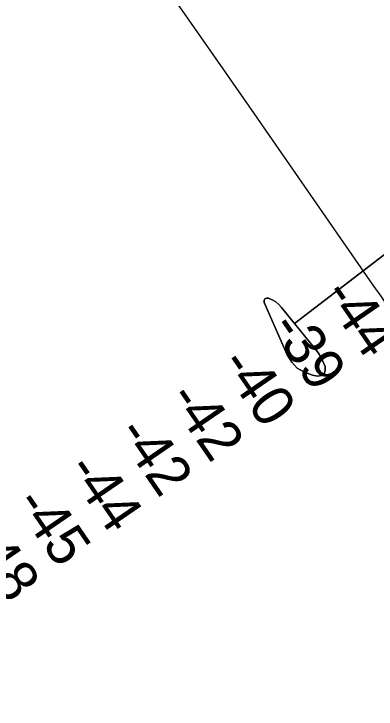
# Model space of a CAD drawing. Extents: x 3892998 to 3931244, y 278583 to 304547.
# Drawn here: x 3912238 to 3912822, y 290539 to 291661 of the extents above; entities that cross this region are included whole.
import ezdxf

# ---------------------------------------------------------------- set-up
doc = ezdxf.new("R2010")
doc.units = 0
for name, color, linetype in [('V-GRID-MAJR', 7, 'Continuous'), ('V-RIVR-EDGE', 7, 'Continuous'), ('V-RIVR-RANG', 7, 'Continuous'), ('V-TOPO-DPTH', 7, 'Continuous'), ('V-TOPO-MAJR', 7, 'Continuous'), ('V-TOPO-MINR', 7, 'Continuous')]:
    doc.layers.add(name, color=color, linetype=linetype)

msp = doc.modelspace()

# ---------------------------------------------------------------- linework, layer by layer
at = {"layer": 'V-GRID-MAJR'}
msp.add_spline([(3897162.9, 290075.2), (3902475.5, 290165.2), (3907788.2, 290256), (3913100.9, 290347.6), (3918413.5, 290440), (3923726.1, 290533.1), (3929038.7, 290627)], degree=3, dxfattribs=at)
at = {"layer": 'V-RIVR-EDGE'}
msp.add_spline([(3909865.8, 290928.2), (3909862.6, 290923.1), (3909860.7, 290922.6), (3909860.7, 290920.7), (3909870.3, 290905.1), (3909881.9, 290877.9), (3909893.5, 290856.5), (3909906.1, 290843.8), (3909921.6, 290817.6), (3909937.1, 290794.7), (3909948.2, 290777.2), (3909977.7, 290734.4), (3910003.4, 290694.5), (3910040.6, 290645.9), (3910078.4, 290595.3), (3910114.2, 290544.2), (3910151.5, 290493.6), (3910182, 290444.5), (3910200.8, 290413.3), (3910226.9, 290368.6), (3910256.9, 290323.8), (3910278.7, 290289.3), (3910307.7, 290250.4), (3910325.2, 290226.5), (3910363.9, 290167.2), (3910391.4, 290124.9), (3910427.7, 290068.9), (3910449.5, 290036.8), (3910504.2, 289956.6), (3910522.1, 289926.9), (3910550.1, 289879.7), (3910562.2, 289857.4), (3910573.3, 289842.3), (3910610.6, 289806.7), (3910620.8, 289794.1), (3910623.2, 289780), (3910634.8, 289764.4), (3910664.8, 289724), (3910692.4, 289689.5), (3910710.8, 289668.1), (3910721, 289660.3), (3910770.9, 289605.3), (3910782.5, 289588.7), (3910807.7, 289548.4), (3910835.7, 289503.6), (3910862.8, 289470), (3910892.3, 289425.8), (3910920.4, 289383.5), (3910948, 289342.6), (3910968.8, 289304.7), (3911000.2, 289260.9), (3911019.6, 289231.7), (3911055.9, 289191.3), (3911085.5, 289159.7), (3911118.9, 289116.8), (3911139.2, 289091.1), (3911161, 289062.3), (3911184.2, 289025.9), (3911223.4, 288981.6), (3911281.5, 288916.4), (3911313, 288876.9), (3911328.5, 288859.4), (3911346.4, 288837.5), (3911371.6, 288801), (3911404.5, 288751.9), (3911426.7, 288715.4), (3911446.6, 288687.7), (3911479, 288646.8), (3911529.4, 288582.1), (3911550.6, 288552.9), (3911609.2, 288468.3), (3911644.5, 288421.1), (3911677, 288378.8), (3911701.2, 288348.1), (3911741.4, 288303.8), (3911770.9, 288264.9), (3911788.8, 288235.7), (3911834.3, 288164.7), (3911857.5, 288130.2), (3911884.6, 288092.7), (3911915.6, 288045.5), (3911921.9, 288035.8), (3911928.6, 288029.9), (3911972.6, 287945.8), (3911992.9, 287906.4), (3912000.6, 287887), (3912014.7, 287866.5), (3912026.8, 287848.1), (3912066.4, 287785.3), (3912084.8, 287750.8), (3912094.5, 287732.8), (3912094.9, 287726), (3912096.8, 287711.4), (3912096.3, 287704.6), (3912095.4, 287700.3), (3912088.6, 287695.9), (3912085.6, 287696.9), (3912073, 287702.3), (3912062.4, 287706.2), (3912054.1, 287706.2), (3912051.2, 287704.3), (3912049.2, 287697.9), (3912054, 287685.8), (3912068.6, 287663.9), (3912113.1, 287586.6), (3912136.7, 287540.9), (3912153.7, 287513.6), (3912163.8, 287503.9), (3912187.6, 287479.6), (3912207.4, 287453.3), (3912216.1, 287446), (3912226.8, 287436.2), (3912240.8, 287416.8), (3912253.4, 287397.8), (3912271.3, 287366.2), (3912283.9, 287341.4), (3912284.8, 287339), (3912290.2, 287338), (3912303.8, 287344.3), (3912317.4, 287350.5), (3912319.8, 287350.5), (3912322.7, 287350.5), (3912327.6, 287345.7), (3912328.5, 287338.4), (3912335.8, 287321.4), (3912348.4, 287300), (3912369.2, 287275.1), (3912380.3, 287265.4), (3912402.1, 287253.2), (3912416.7, 287243.5), (3912434.2, 287238.1), (3912456.9, 287220), (3912481.6, 287183.6), (3912501.9, 287148.1), (3912512.6, 287124.7), (3912531.4, 287085.8), (3912550.3, 287059.6), (3912569.6, 287034.3), (3912593.3, 286996.8), (3912613.7, 286968.1), (3912632, 286936.5), (3912645.1, 286912.7), (3912660.6, 286888.8), (3912675.1, 286867.4), (3912698.3, 286835.3), (3912720.1, 286784.8), (3912737, 286747.8), (3912742.3, 286740), (3912755.3, 286715.2), (3912761.6, 286696.8), (3912774.1, 286660.3), (3912779.9, 286635.5), (3912793.4, 286585.5), (3912797.2, 286569.4), (3912804, 286543.7), (3912804.4, 286532)], degree=3, dxfattribs=at)
at = {"layer": 'V-TOPO-DPTH'}
for points in [[(3913033.3, 291425), (3912690.2, 291161.4), (3912669.3, 291187.3), (3912664.7, 291192.1), (3912659.8, 291196.3), (3912654.2, 291199.7), (3912648.2, 291202.6), (3912644.7, 291202.4), (3912642.2, 291201.3), (3912641.2, 291198.7), (3912641.1, 291195.2), (3912678.2, 291110.8), (3912685.6, 291099.1), (3912694.6, 291089.4), (3912706, 291082.7), (3912719, 291078.1), (3912727, 291076.5), (3912733.4, 291077.7), (3912737.8, 291080.5)], [(3912737.8, 291080.5), (3912739.5, 291085.4), (3912739.3, 291091.9), (3912734.4, 291102.8), (3912732.4, 291107.1), (3912730.1, 291111.1), (3912727.5, 291115), (3912724.7, 291118.8), (3912693, 291157.9), (3912690.2, 291161.4), (3913033.3, 291425), (3913036.6, 291419.3)], [(3912737.8, 291080.5), (3912733.4, 291077.7), (3912727, 291076.5), (3912719, 291078.1), (3912706, 291082.7), (3912694.6, 291089.4), (3912685.6, 291099.1), (3912678.2, 291110.8), (3912641.1, 291195.2), (3912641.2, 291198.7), (3912642.2, 291201.3), (3912644.7, 291202.4), (3912648.2, 291202.6), (3912654.2, 291199.7), (3912659.8, 291196.3), (3912664.7, 291192.1), (3912669.3, 291187.3), (3912724.7, 291118.8), (3912727.5, 291115), (3912730.1, 291111.1), (3912732.4, 291107.1), (3912734.4, 291102.8), (3912739.3, 291091.9), (3912739.5, 291085.4), (3912737.8, 291080.5)]]:
    msp.add_lwpolyline(points, dxfattribs=at)
at = {"layer": 'V-TOPO-MAJR'}
msp.add_lwpolyline([(3912484.1, 291702), (3912531, 291634.5), (3912578, 291567), (3912624.9, 291499.6), (3912816.6, 291223.4), (3912829.1, 291205.4), (3912841.6, 291187.2), (3912853.9, 291169), (3912866.1, 291150.8), (3913227, 290610.6), (3913234.3, 290599.6), (3913241.7, 290588.5), (3913249, 290577.5), (3913256.4, 290566.4), (3913263.8, 290555.4), (3913271.3, 290544.5), (3913279, 290533.7), (3913286.9, 290522.9), (3913293.4, 290514.1), (3913304.6, 290499), (3913315.6, 290483.8), (3913326.4, 290468.5), (3913337.2, 290453.1), (3913674.7, 289963.4)], dxfattribs=at)
at = {"layer": 'V-TOPO-MINR'}
msp.add_lwpolyline([(3912737.8, 291080.5), (3912733.4, 291077.7), (3912727, 291076.5), (3912719, 291078.1), (3912706, 291082.7), (3912694.6, 291089.4), (3912685.6, 291099.1), (3912678.2, 291110.8), (3912641.1, 291195.2), (3912641.2, 291198.7), (3912642.2, 291201.3), (3912644.7, 291202.4), (3912648.2, 291202.6), (3912654.2, 291199.7), (3912659.8, 291196.3), (3912664.7, 291192.1), (3912669.3, 291187.3), (3912724.7, 291118.8), (3912727.5, 291115), (3912730.1, 291111.1), (3912732.4, 291107.1), (3912734.4, 291102.8), (3912739.3, 291091.9), (3912739.5, 291085.4), (3912737.8, 291080.5)], dxfattribs=at)
msp.add_lwpolyline([(3912737.8, 291080.5), (3912733.4, 291077.7), (3912727, 291076.5), (3912719, 291078.1), (3912706, 291082.7), (3912694.6, 291089.4), (3912685.6, 291099.1), (3912678.2, 291110.8), (3912641.1, 291195.2), (3912641.2, 291198.7), (3912642.2, 291201.3), (3912644.7, 291202.4), (3912648.2, 291202.6), (3912654.2, 291199.7), (3912659.8, 291196.3), (3912664.7, 291192.1), (3912669.3, 291187.3), (3912724.7, 291118.8), (3912727.5, 291115), (3912730.1, 291111.1), (3912732.4, 291107.1), (3912734.4, 291102.8), (3912739.3, 291091.9), (3912739.5, 291085.4), (3912737.8, 291080.5)], dxfattribs=at)

# ---------------------------------------------------------------- texts
at = {"layer": 'V-RIVR-RANG'}
for s, p in [('-44', (3912733.6, 291207.9)), ('-39', (3912648.9, 291154.6)), ('-40', (3912567.9, 291096)), ('-42', (3912484.2, 291041.1)), ('-42', (3912401.6, 290984.7)), ('-44', (3912320.7, 290926)), ('-45', (3912237.1, 290871.1)), ('-48', (3912155.1, 290813.8))]:
    msp.add_text(s, height=67, rotation=304.473, dxfattribs=at).set_placement(p)

doc.saveas('drawing.dxf')
